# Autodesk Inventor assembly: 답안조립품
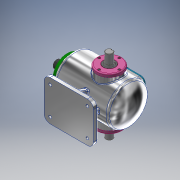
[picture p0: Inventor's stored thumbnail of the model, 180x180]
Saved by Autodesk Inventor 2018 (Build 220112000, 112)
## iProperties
Created: 2021-11
Part Number: 답안조립품
Document SubType Name: Assembly
Designer: 1class2
Author: 1class2
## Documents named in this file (14)
- C:\Users\1class2\Desktop\711106V1043\답안조립품.iam
- C:\Users\1class2\Desktop\711106V1043\본체.ipt
- C:\Users\1class2\Desktop\711106V1043\베어링 6205.ipt
- 베어링 6205.ipt
- C:\Users\1class2\Desktop\711106V1043\축 커버.ipt
- C:\Users\1class2\Desktop\711106V1043\오일실.ipt
- 오일실.ipt
- C:\Users\1class2\Desktop\711106V1043\슬라이드 커버.ipt
- C:\Users\1class2\Desktop\711106V1043\부시.ipt
- C:\Users\1class2\Desktop\711106V1043\슬라이드.ipt
- C:\Users\1class2\Desktop\711106V1043\편심축.ipt
- C:\Users\1class2\Desktop\711106V1043\상부커버.ipt
- C:\Users\1class2\Desktop\711106V1043\육각머리볼트 M4.ipt
- C:\Users\1class2\Desktop\711106V1043\볼트 M4x0.7.ipt
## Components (8 placed, 1 different names)
1. M4x0.7:5
2. M4x0.7:6
3. M4x0.7:7
4. M4x0.7:8
5. M4x0.7:9
6. M4x0.7:10
7. M4x0.7:11
8. M4x0.7:12
